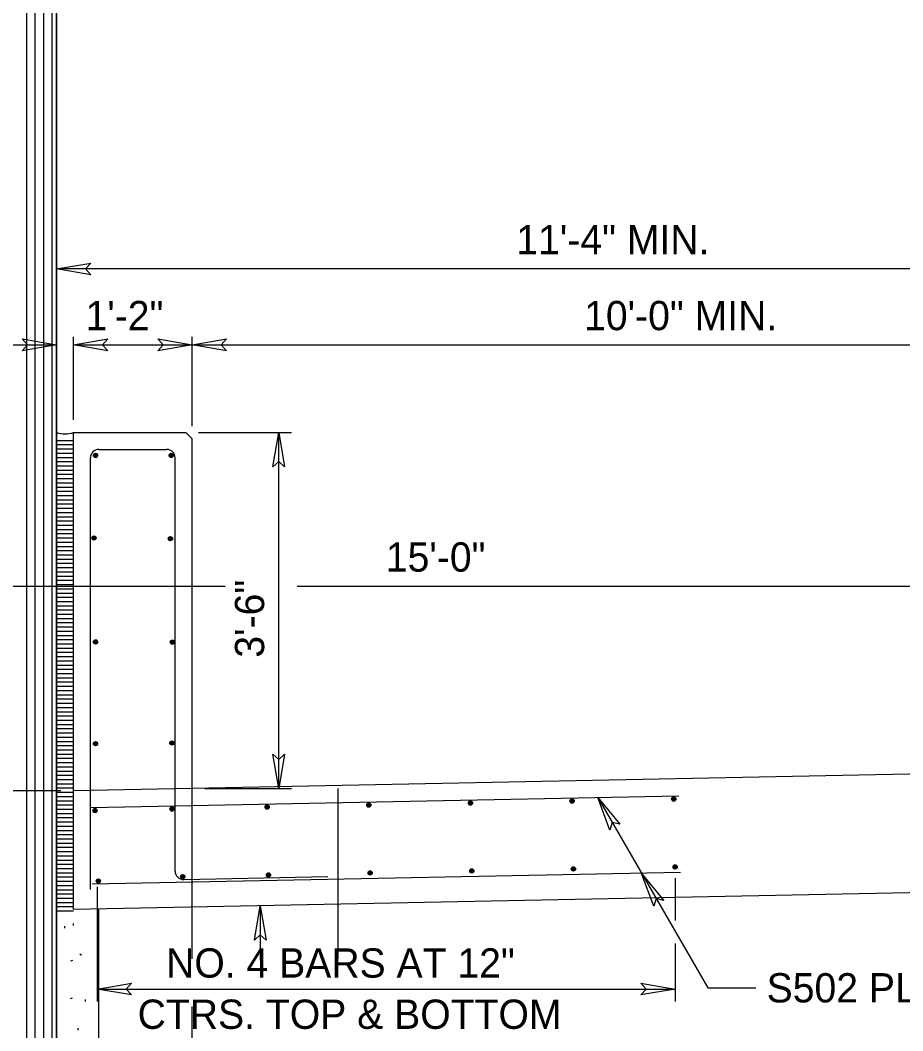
# Model space of a CAD drawing. Extents: x 99836 to 115004, y 99786 to 102182.
# Drawn here: x 114332 to 114694, y 100812.2 to 101226.5 of the extents above; entities that cross this region are included whole.
import ezdxf

# ---------------------------------------------------------------- set-up
doc = ezdxf.new("R2010")
doc.units = 0
doc.layers.add('Border Organizer Shape', color=7, linetype='Continuous')

msp = doc.modelspace()

# ---------------------------------------------------------------- linework, layer by layer
at = {"layer": 'Border Organizer Shape'}
for p, q in [((114346.86, 101022.73), (114346.86, 101467.55)), ((114334.65, 100612.67), (114334.65, 101411.95)), ((114338.13, 100612.67), (114338.13, 101411.95)), ((114341.6, 100612.67), (114341.6, 101411.95)), ((114345.08, 100612.67), (114345.08, 101411.95)), ((114819.48, 101124.52), (114346.86, 101124.52)), ((114346.86, 101027.94), (114346.86, 101094.98)), ((114353.81, 101062.7), (114353.81, 101096.63)), ((114402.47, 101060.09), (114402.47, 101096.63)), ((114293.66, 101093.4), (114346.86, 101093.4)), ((114353.81, 101093.4), (114402.47, 101093.4)), ((114402.47, 101093.4), (114819.48, 101093.4)), ((114346.86, 101027.94), (114346.86, 101063.86)), ((114353.81, 100861.9), (114353.81, 101057.48)), ((114353.81, 101057.48), (114399.86, 101057.48)), ((114402.47, 101054.88), (114399.86, 101057.48)), ((114405.07, 101057.48), (114443.24, 101057.48)), ((114438.03, 100911.53), (114438.03, 101057.48)), ((114346.86, 101054.22), (114353.81, 101054.22)), ((114402.47, 100911.53), (114402.47, 101054.88)), ((114346.86, 101052.48), (114353.81, 101052.48)), ((114346.86, 101050.74), (114353.81, 101050.74)), ((114364.24, 101050.53), (114392.04, 101050.53)), ((114346.86, 101049), (114353.81, 101049)), ((114346.86, 101047.27), (114353.81, 101047.27)), ((114346.86, 101045.53), (114353.81, 101045.53)), ((114360.76, 100870.08), (114360.76, 101047.06)), ((114361.99, 101048.05), (114363.73, 101048.05)), ((114362.86, 101048.05), (114362.25, 101048.66)), ((114362.86, 101048.05), (114362.25, 101047.43)), ((114362.86, 101047.18), (114362.86, 101048.92)), ((114362.86, 101048.05), (114363.48, 101048.66)), ((114362.86, 101048.05), (114362.86, 101048.05)), ((114362.86, 101048.05), (114363.48, 101047.43)), ((114393.03, 101048.05), (114394.77, 101048.05)), ((114393.9, 101048.05), (114393.28, 101048.66)), ((114393.9, 101048.05), (114393.28, 101047.43)), ((114393.9, 101047.18), (114393.9, 101048.92)), ((114393.9, 101048.05), (114394.51, 101048.66)), ((114393.9, 101048.05), (114393.9, 101048.05)), ((114393.9, 101048.05), (114394.51, 101047.43)), ((114395.52, 100877.61), (114395.52, 101047.06)), ((114346.86, 101043.79), (114353.81, 101043.79)), ((114346.86, 101042.05), (114353.81, 101042.05)), ((114346.86, 101040.32), (114353.81, 101040.32)), ((114346.86, 101038.58), (114353.81, 101038.58)), ((114346.86, 101036.84), (114353.81, 101036.84)), ((114346.86, 101035.1), (114353.81, 101035.1)), ((114346.86, 101033.37), (114353.81, 101033.37)), ((114346.86, 101031.63), (114353.81, 101031.63)), ((114346.86, 101029.89), (114353.81, 101029.89)), ((114346.86, 101028.15), (114353.81, 101028.15)), ((114346.86, 101026.42), (114353.81, 101026.42)), ((114346.86, 101024.68), (114353.81, 101024.68)), ((114346.86, 101022.94), (114353.81, 101022.94)), ((114346.86, 100612.67), (114346.86, 101022.73)), ((114346.86, 101021.2), (114353.81, 101021.2)), ((114346.86, 101019.47), (114353.81, 101019.47)), ((114346.86, 101017.73), (114353.81, 101017.73)), ((114346.86, 101015.99), (114353.81, 101015.99)), ((114346.86, 101014.25), (114353.81, 101014.25)), ((114346.86, 101012.52), (114353.81, 101012.52)), ((114361.38, 101014.23), (114363.12, 101014.23)), ((114362.25, 101014.23), (114361.64, 101014.84)), ((114362.25, 101014.23), (114361.64, 101013.61)), ((114362.25, 101013.36), (114362.25, 101015.09)), ((114362.25, 101014.23), (114362.87, 101014.84)), ((114362.25, 101014.23), (114362.25, 101014.23)), ((114362.25, 101014.23), (114362.87, 101013.61)), ((114392.7, 101013.93), (114394.44, 101013.93)), ((114393.57, 101013.93), (114392.95, 101014.54)), ((114393.57, 101013.93), (114392.95, 101013.32)), ((114393.57, 101013.07), (114393.57, 101014.8)), ((114393.57, 101013.93), (114394.18, 101014.54)), ((114393.57, 101013.93), (114393.57, 101013.93)), ((114393.57, 101013.93), (114394.18, 101013.32)), ((114346.86, 101010.78), (114353.81, 101010.78)), ((114346.86, 101009.04), (114353.81, 101009.04)), ((114346.86, 101007.3), (114353.81, 101007.3)), ((114346.86, 101005.57), (114353.81, 101005.57)), ((114346.86, 101003.83), (114353.81, 101003.83)), ((114346.86, 101002.09), (114353.81, 101002.09)), ((114346.86, 101000.35), (114353.81, 101000.35)), ((114346.86, 100998.62), (114353.81, 100998.62)), ((114346.86, 100996.88), (114353.81, 100996.88)), ((114193.96, 100994.42), (114416.02, 100994.42)), ((114346.86, 100995.14), (114353.81, 100995.14)), ((114346.86, 100993.4), (114353.81, 100993.4)), ((114346.86, 100991.66), (114353.81, 100991.66)), ((114445.61, 100994.42), (114819.48, 100994.42)), ((114346.86, 100989.93), (114353.81, 100989.93)), ((114346.86, 100988.19), (114353.81, 100988.19)), ((114346.86, 100986.45), (114353.81, 100986.45)), ((114346.86, 100984.71), (114353.81, 100984.71)), ((114346.86, 100982.98), (114353.81, 100982.98)), ((114346.86, 100981.24), (114353.81, 100981.24)), ((114346.86, 100979.5), (114353.81, 100979.5)), ((114346.86, 100977.76), (114353.81, 100977.76)), ((114346.86, 100976.03), (114353.81, 100976.03)), ((114346.86, 100974.29), (114353.81, 100974.29)), ((114346.86, 100972.55), (114353.81, 100972.55)), ((114346.86, 100970.81), (114353.81, 100970.81)), ((114361.99, 100971.6), (114363.73, 100971.6)), ((114362.86, 100971.6), (114362.25, 100972.21)), ((114362.86, 100971.6), (114362.25, 100970.98)), ((114362.86, 100970.73), (114362.86, 100972.47)), ((114362.86, 100971.6), (114363.48, 100972.21)), ((114362.86, 100971.6), (114362.86, 100971.6)), ((114362.86, 100971.6), (114363.48, 100970.98)), ((114393.51, 100971.51), (114395.25, 100971.51)), ((114394.38, 100971.51), (114393.76, 100972.12)), ((114394.38, 100971.51), (114393.76, 100970.89)), ((114394.38, 100970.64), (114394.38, 100972.38)), ((114394.38, 100971.51), (114394.99, 100972.12)), ((114394.38, 100971.51), (114394.38, 100971.51)), ((114394.38, 100971.51), (114394.99, 100970.89)), ((114346.86, 100969.08), (114353.81, 100969.08)), ((114346.86, 100967.34), (114353.81, 100967.34)), ((114346.86, 100965.6), (114353.81, 100965.6)), ((114346.86, 100963.86), (114353.81, 100963.86)), ((114346.86, 100962.13), (114353.81, 100962.13)), ((114346.86, 100960.39), (114353.81, 100960.39)), ((114346.86, 100958.65), (114353.81, 100958.65)), ((114346.86, 100956.91), (114353.81, 100956.91)), ((114346.86, 100955.18), (114353.81, 100955.18)), ((114346.86, 100953.44), (114353.81, 100953.44)), ((114346.86, 100951.7), (114353.81, 100951.7)), ((114346.86, 100949.96), (114353.81, 100949.96)), ((114346.86, 100948.23), (114353.81, 100948.23)), ((114346.86, 100946.49), (114353.81, 100946.49)), ((114346.86, 100944.75), (114353.81, 100944.75)), ((114346.86, 100943.01), (114353.81, 100943.01)), ((114346.86, 100941.28), (114353.81, 100941.28)), ((114346.86, 100939.54), (114353.81, 100939.54)), ((114346.86, 100937.8), (114353.81, 100937.8)), ((114346.86, 100936.06), (114353.81, 100936.06)), ((114346.86, 100934.33), (114353.81, 100934.33)), ((114346.86, 100932.59), (114353.81, 100932.59)), ((114346.86, 100930.85), (114353.81, 100930.85)), ((114346.86, 100929.11), (114353.81, 100929.11)), ((114361.99, 100929.9), (114363.73, 100929.9)), ((114362.86, 100929.9), (114362.25, 100930.51)), ((114362.86, 100929.9), (114362.25, 100929.28)), ((114362.86, 100929.03), (114362.86, 100930.77)), ((114362.86, 100929.9), (114363.48, 100930.51)), ((114362.86, 100929.9), (114362.86, 100929.9)), ((114362.86, 100929.9), (114363.48, 100929.28)), ((114393.32, 100930.18), (114395.06, 100930.18)), ((114394.19, 100930.18), (114393.57, 100930.79)), ((114394.19, 100930.18), (114393.57, 100929.56)), ((114394.19, 100929.31), (114394.19, 100931.05)), ((114394.19, 100930.18), (114394.8, 100930.79)), ((114394.19, 100930.18), (114394.19, 100930.18)), ((114394.19, 100930.18), (114394.8, 100929.56)), ((114346.86, 100927.37), (114353.81, 100927.37)), ((114346.86, 100925.64), (114353.81, 100925.64)), ((114346.86, 100923.9), (114353.81, 100923.9)), ((114346.86, 100922.16), (114353.81, 100922.16)), ((114346.86, 100920.42), (114353.81, 100920.42)), ((114346.86, 100918.69), (114353.81, 100918.69)), ((114346.86, 100916.95), (114353.81, 100916.95)), ((114819.48, 100919.78), (114402.47, 100911.53)), ((114346.86, 100915.21), (114353.81, 100915.21)), ((114346.86, 100913.47), (114353.81, 100913.47)), ((114348.61, 100910.56), (114213.4, 100910.56)), ((114348.61, 100910.56), (114248.88, 100910.56)), ((114346.86, 100911.74), (114353.81, 100911.74)), ((114346.86, 100910), (114353.81, 100910)), ((114402.47, 100911.53), (114353.83, 100910.56)), ((114360.91, 100903.75), (114602.12, 100908.53)), ((114402.47, 100841.64), (114402.47, 100911.53)), ((114407.68, 100911.53), (114443.24, 100911.53)), ((114462.41, 100841.64), (114462.41, 100911.53)), ((114346.86, 100908.26), (114353.81, 100908.26)), ((114346.86, 100906.52), (114353.81, 100906.52)), ((114346.86, 100904.79), (114353.81, 100904.79)), ((114433.26, 100903.88), (114432.64, 100904.47)), ((114433.28, 100903.01), (114433.25, 100904.75)), ((114433.26, 100903.88), (114433.87, 100904.5)), ((114474.09, 100904.68), (114475.83, 100904.72)), ((114474.96, 100904.7), (114474.33, 100905.3)), ((114474.96, 100904.7), (114474.35, 100904.07)), ((114474.98, 100903.83), (114474.94, 100905.57)), ((114474.96, 100904.7), (114475.56, 100905.33)), ((114474.96, 100904.7), (114474.96, 100904.7)), ((114474.96, 100904.7), (114475.58, 100904.1)), ((114515.78, 100905.51), (114517.52, 100905.54)), ((114516.65, 100905.52), (114516.03, 100906.13)), ((114516.65, 100905.52), (114516.05, 100904.9)), ((114516.67, 100904.65), (114516.64, 100906.39)), ((114516.65, 100905.52), (114517.26, 100906.15)), ((114516.65, 100905.52), (114516.65, 100905.52)), ((114516.65, 100905.52), (114517.28, 100904.92)), ((114557.48, 100906.33), (114559.21, 100906.36)), ((114558.35, 100906.35), (114557.72, 100906.96)), ((114558.35, 100906.35), (114557.74, 100905.72)), ((114558.36, 100905.48), (114558.32, 100907.22)), ((114558.35, 100906.35), (114558.95, 100906.98)), ((114558.35, 100906.35), (114558.35, 100906.35)), ((114558.35, 100906.35), (114558.97, 100905.75)), ((114568.83, 100907.87), (114614.02, 100829.82)), ((114599.17, 100907.16), (114600.91, 100907.2)), ((114600.04, 100907.18), (114599.41, 100907.77)), ((114600.04, 100907.18), (114599.44, 100906.55)), ((114600.06, 100906.3), (114600.02, 100908.04)), ((114600.04, 100907.18), (114600.64, 100907.8)), ((114600.04, 100907.18), (114600.04, 100907.18)), ((114600.04, 100907.18), (114600.67, 100906.57)), ((114346.86, 100903.05), (114353.81, 100903.05)), ((114346.86, 100901.31), (114353.81, 100901.31)), ((114361.77, 100902.46), (114363.5, 100902.49)), ((114362.63, 100902.48), (114362.01, 100903.08)), ((114362.63, 100902.48), (114362.03, 100901.85)), ((114362.65, 100901.61), (114362.61, 100903.35)), ((114362.63, 100902.48), (114363.24, 100903.11)), ((114362.63, 100902.48), (114362.63, 100902.48)), ((114362.63, 100902.48), (114363.26, 100901.87)), ((114393.37, 100903.04), (114395.11, 100903.06)), ((114394.24, 100903.05), (114393.6, 100903.65)), ((114394.24, 100903.05), (114393.63, 100902.42)), ((114394.25, 100902.18), (114394.22, 100903.92)), ((114394.24, 100903.05), (114394.83, 100903.67)), ((114394.24, 100903.05), (114394.24, 100903.05)), ((114394.24, 100903.05), (114394.86, 100902.44)), ((114432.39, 100903.86), (114434.13, 100903.89)), ((114433.26, 100903.88), (114432.66, 100903.24)), ((114433.26, 100903.88), (114433.26, 100903.88)), ((114433.26, 100903.88), (114433.89, 100903.27)), ((114346.86, 100899.57), (114353.81, 100899.57)), ((114346.86, 100897.84), (114353.81, 100897.84)), ((114346.86, 100896.1), (114353.81, 100896.1)), ((114346.86, 100894.36), (114353.81, 100894.36)), ((114346.86, 100892.62), (114353.81, 100892.62)), ((114346.86, 100890.89), (114353.81, 100890.89)), ((114346.86, 100889.15), (114353.81, 100889.15)), ((114346.86, 100887.41), (114353.81, 100887.41)), ((114346.86, 100885.67), (114353.81, 100885.67)), ((114346.86, 100883.94), (114353.81, 100883.94)), ((114346.86, 100882.2), (114353.81, 100882.2)), ((114346.86, 100880.46), (114353.81, 100880.46)), ((114558.92, 100877.69), (114558.88, 100879.43)), ((114599.72, 100879.36), (114601.46, 100879.39)), ((114600.59, 100879.38), (114599.96, 100879.98)), ((114600.59, 100879.38), (114599.98, 100878.75)), ((114600.61, 100878.51), (114600.57, 100880.25)), ((114600.59, 100879.38), (114601.19, 100880)), ((114600.59, 100879.38), (114600.59, 100879.38)), ((114600.59, 100879.38), (114601.22, 100878.78)), ((114346.86, 100878.72), (114353.81, 100878.72)), ((114346.86, 100876.99), (114353.81, 100876.99)), ((114346.86, 100875.25), (114353.81, 100875.25)), ((114361.53, 100872.48), (114602.74, 100877.26)), ((114397.79, 100875.37), (114399.53, 100875.4)), ((114398.66, 100875.39), (114398.03, 100875.99)), ((114398.66, 100875.39), (114398.05, 100874.76)), ((114398.67, 100874.52), (114398.64, 100876.26)), ((114398.66, 100875.39), (114399.26, 100876.01)), ((114398.66, 100875.39), (114398.66, 100875.39)), ((114398.66, 100875.39), (114399.28, 100874.78)), ((114399.05, 100874.21), (114458.12, 100875.38)), ((114432.95, 100876.06), (114434.69, 100876.1)), ((114433.82, 100876.08), (114433.19, 100876.68)), ((114433.82, 100876.08), (114433.21, 100875.45)), ((114433.83, 100875.21), (114433.8, 100876.94)), ((114433.82, 100876.08), (114434.42, 100876.71)), ((114433.82, 100876.08), (114433.82, 100876.08)), ((114433.82, 100876.08), (114434.44, 100875.48)), ((114474.64, 100876.89), (114476.37, 100876.92)), ((114475.51, 100876.9), (114474.88, 100877.51)), ((114475.51, 100876.9), (114474.91, 100876.28)), ((114475.53, 100876.03), (114475.49, 100877.77)), ((114475.51, 100876.9), (114476.11, 100877.53)), ((114475.51, 100876.9), (114475.51, 100876.9)), ((114475.51, 100876.9), (114476.14, 100876.3)), ((114516.33, 100877.71), (114518.07, 100877.74)), ((114517.2, 100877.73), (114516.58, 100878.33)), ((114517.2, 100877.73), (114516.6, 100877.1)), ((114517.22, 100876.86), (114517.19, 100878.6)), ((114517.2, 100877.73), (114517.8, 100878.36)), ((114517.2, 100877.73), (114517.2, 100877.73)), ((114517.2, 100877.73), (114517.83, 100877.13)), ((114558.03, 100878.54), (114559.76, 100878.57)), ((114558.9, 100878.56), (114558.27, 100879.15)), ((114558.9, 100878.56), (114558.29, 100877.92)), ((114558.9, 100878.56), (114559.5, 100879.18)), ((114558.9, 100878.56), (114558.9, 100878.56)), ((114558.9, 100878.56), (114559.52, 100877.95)), ((114346.86, 100873.51), (114353.81, 100873.51)), ((114346.86, 100871.77), (114353.81, 100871.77)), ((114819.48, 100871.12), (114353.81, 100861.9)), ((114363.15, 100873.59), (114364.89, 100873.62)), ((114364.02, 100873.6), (114363.39, 100874.21)), ((114364.02, 100873.6), (114363.41, 100872.98)), ((114363.56, 100871.22), (114363.56, 100824.24)), ((114364.04, 100872.74), (114364, 100874.47)), ((114364.02, 100873.6), (114364.62, 100874.23)), ((114364.02, 100873.6), (114364.02, 100873.6)), ((114364.02, 100873.6), (114364.64, 100873)), ((114600.58, 100874.78), (114600.58, 100857.43)), ((114346.86, 100870.04), (114353.81, 100870.04)), ((114346.86, 100868.3), (114353.81, 100868.3)), ((114346.86, 100866.56), (114353.81, 100866.56)), ((114346.86, 100864.82), (114353.81, 100864.82)), ((114346.86, 100863.09), (114353.81, 100863.09)), ((114430.45, 100863.41), (114430.45, 100841)), ((114346.86, 100861.35), (114353.81, 100861.35)), ((114364.24, 100612.67), (114364.24, 100862.11)), ((114350.14, 100855.08), (114350.1, 100854.27)), ((114353.74, 100856.18), (114353.7, 100855.37)), ((114600.58, 100847.92), (114600.58, 100824.24)), ((114357.07, 100843.1), (114356.43, 100843.54)), ((114352.77, 100840.83), (114353.52, 100841.19)), ((114363.79, 100836.27), (114364.24, 100836.49)), ((114614.02, 100829.82), (114633.67, 100829.82)), ((114352.64, 100825.37), (114353.39, 100825.73)), ((114363.56, 100829.28), (114600.58, 100829.28)), ((114358.66, 100824.98), (114358.62, 100824.18)), ((114402.47, 100764.31), (114402.47, 100822.2)), ((114355.63, 100813.27), (114355.59, 100812.46))]:
    msp.add_line(p, q, dxfattribs=at)
for points in [[(114319.06, 101411.95), (114346.86, 101411.95), (114346.86, 100612.67), (114319.06, 100612.67)], [(114360.97, 101122.13), (114346.86, 101124.52), (114360.97, 101126.91), (114358.75, 101124.52)], [(114332.76, 101095.79), (114346.86, 101093.4), (114332.76, 101091), (114334.98, 101093.4)], [(114367.92, 101091), (114353.81, 101093.4), (114367.92, 101095.79), (114365.7, 101093.4)], [(114388.36, 101095.79), (114402.47, 101093.4), (114388.36, 101091), (114390.58, 101093.4)], [(114416.57, 101091), (114402.47, 101093.4), (114416.57, 101095.79), (114414.35, 101093.4)], [(114435.64, 101043.38), (114438.03, 101057.48), (114440.43, 101043.38), (114438.03, 101045.6)], [(114440.42, 100925.63), (114438.03, 100911.53), (114435.64, 100925.63), (114438.03, 100923.41)], [(114573.82, 100894.46), (114568.83, 100907.87), (114577.97, 100896.86), (114574.78, 100897.58)], [(114591.84, 100863.25), (114586.85, 100876.65), (114595.99, 100865.65), (114592.81, 100866.37)], [(114428.06, 100849.31), (114430.45, 100863.41), (114432.85, 100849.31), (114430.45, 100851.53)], [(114377.66, 100826.89), (114363.56, 100829.28), (114377.66, 100831.67), (114375.44, 100829.28)], [(114586.47, 100831.67), (114600.58, 100829.28), (114586.47, 100826.89), (114588.69, 100829.28)]]:
    msp.add_lwpolyline(points, close=True, dxfattribs=at)
for centre, radius in [((114362.86, 101048.05), 0.869), ((114362.86, 101048.05), 0.652), ((114362.86, 101048.05), 0.434), ((114393.89, 101048.05), 0.869), ((114393.89, 101048.05), 0.652), ((114393.89, 101048.05), 0.434), ((114362.25, 101014.22), 0.869), ((114362.25, 101014.22), 0.652), ((114362.25, 101014.22), 0.434), ((114393.57, 101013.93), 0.869), ((114393.57, 101013.93), 0.652), ((114393.57, 101013.93), 0.434), ((114362.86, 100971.6), 0.869), ((114362.86, 100971.6), 0.652), ((114362.86, 100971.6), 0.434), ((114394.38, 100971.51), 0.869), ((114394.38, 100971.51), 0.652), ((114394.38, 100971.51), 0.434), ((114362.86, 100929.89), 0.869), ((114362.86, 100929.89), 0.652), ((114362.86, 100929.89), 0.434), ((114394.18, 100930.18), 0.869), ((114394.18, 100930.18), 0.652), ((114394.18, 100930.18), 0.434), ((114433.26, 100903.87), 0.869), ((114433.26, 100903.87), 0.652), ((114433.26, 100903.87), 0.434), ((114474.96, 100904.7), 0.869), ((114474.96, 100904.7), 0.652), ((114474.96, 100904.7), 0.434), ((114516.65, 100905.52), 0.869), ((114516.65, 100905.52), 0.652), ((114516.65, 100905.52), 0.434), ((114558.34, 100906.35), 0.869), ((114558.34, 100906.35), 0.652), ((114558.34, 100906.35), 0.434), ((114600.04, 100907.17), 0.869), ((114600.04, 100907.17), 0.652), ((114600.04, 100907.17), 0.434), ((114362.63, 100902.47), 0.869), ((114362.63, 100902.47), 0.652), ((114362.63, 100902.47), 0.434), ((114394.23, 100903.05), 0.869), ((114394.23, 100903.05), 0.652), ((114394.23, 100903.05), 0.434), ((114558.89, 100878.55), 0.869), ((114600.59, 100879.38), 0.869), ((114600.59, 100879.38), 0.652), ((114600.59, 100879.38), 0.434), ((114398.65, 100875.38), 0.869), ((114398.65, 100875.38), 0.652), ((114398.65, 100875.38), 0.434), ((114433.81, 100876.08), 0.869), ((114433.81, 100876.08), 0.652), ((114433.81, 100876.08), 0.434), ((114475.51, 100876.9), 0.869), ((114475.51, 100876.9), 0.652), ((114475.51, 100876.9), 0.434), ((114517.2, 100877.73), 0.869), ((114517.2, 100877.73), 0.652), ((114517.2, 100877.73), 0.434), ((114558.89, 100878.55), 0.652), ((114558.89, 100878.55), 0.434), ((114364.02, 100873.6), 0.869), ((114364.02, 100873.6), 0.652), ((114364.02, 100873.6), 0.434)]:
    msp.add_circle(centre, radius, dxfattribs=at)
for centre, radius, start, end in [((114350.34, 101067.1), 10.23, 250.1456, 289.8544), ((114364.24, 101047.06), 3.48, 90, 180), ((114392.04, 101047.06), 3.48, 0, 90), ((114398.99, 100877.68), 3.48, 181.1338, 271.1338)]:
    msp.add_arc(centre, radius, start, end, dxfattribs=at)

# ---------------------------------------------------------------- texts
for s, p in [('11\'-4" MIN.', (114535.45, 101130.52)), ('1\'-2"', (114358.77, 101099.4)), ('10\'-0" MIN.', (114563.26, 101099.4)), ('15\'-0"', (114481.94, 101000.42)), ('NO. 4 BARS AT 12" ', (114391.81, 100833.99)), (' S502 PLACED AT 12" CTRS.', (114633.67, 100823.82)), ('CTRS. TOP & BOTTOM', (114380.14, 100812.99))]:
    msp.add_text(s, height=12, dxfattribs=at).set_placement(p)
msp.add_text('3\'-6"', height=12, rotation=90, dxfattribs=at).set_placement((114432.03, 100965.14))

doc.saveas('drawing.dxf')
